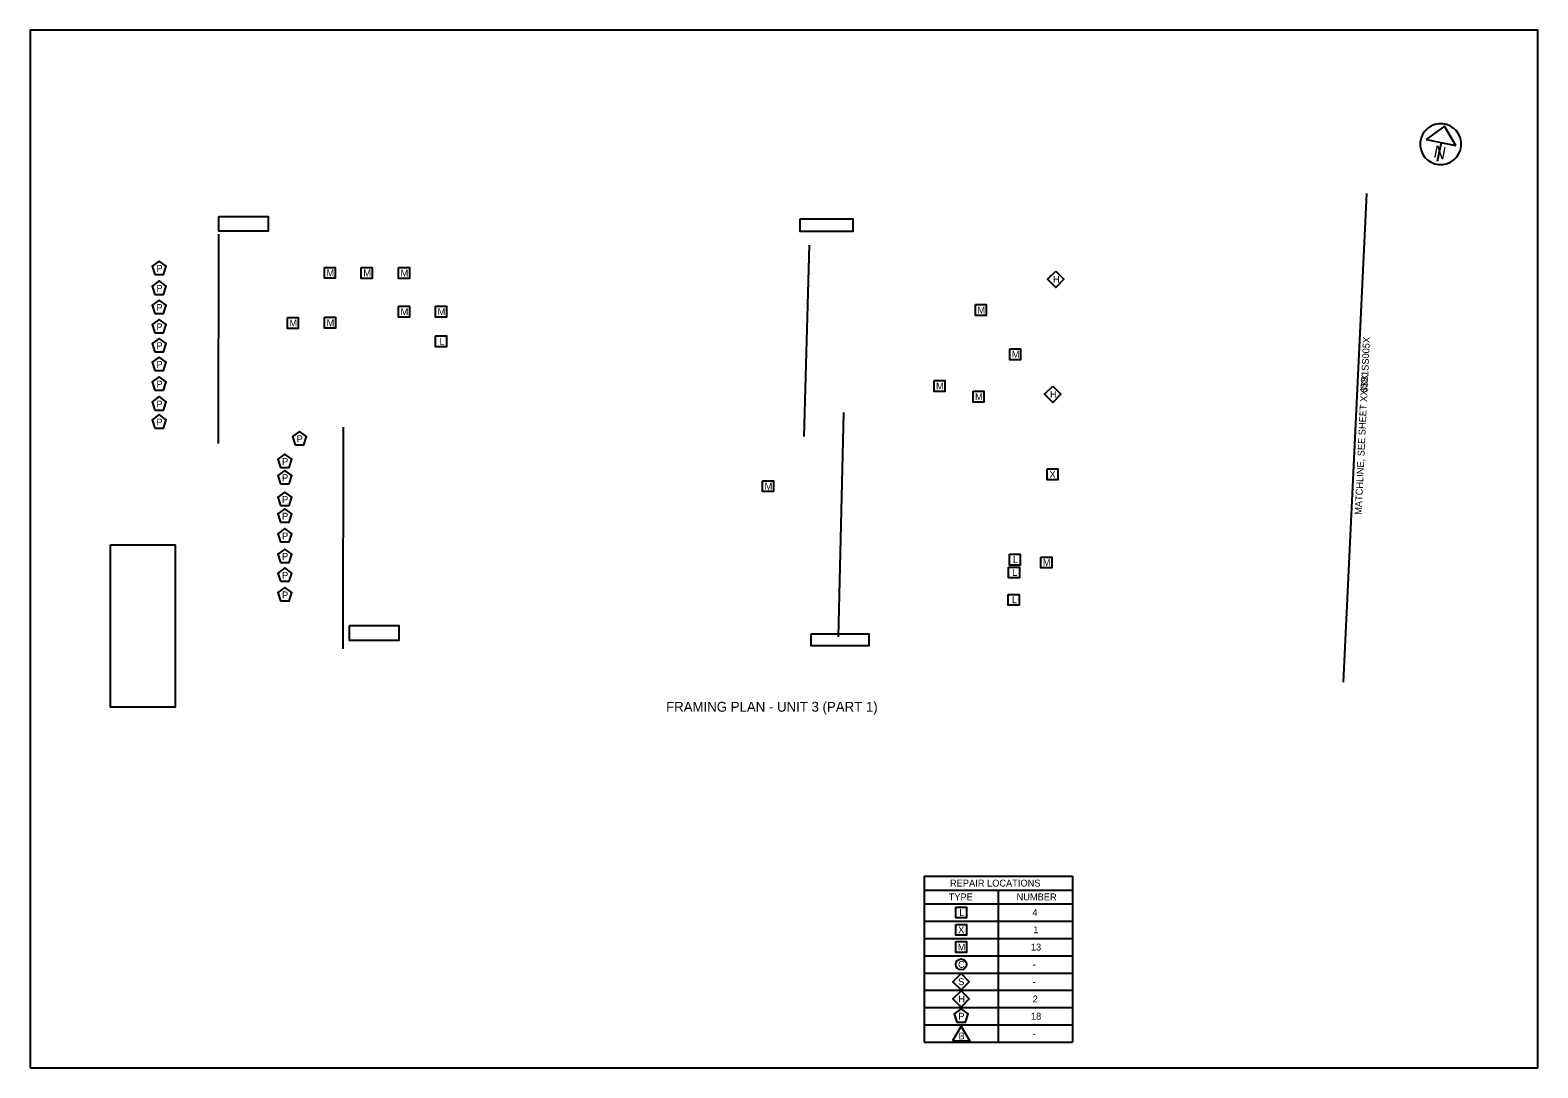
# Model space of a CAD drawing. Extents: x 100 to 130.5, y 100 to 121.
import ezdxf

# ---------------------------------------------------------------- set-up
doc = ezdxf.new("R2010")
doc.units = 0
for name, color, linetype in [('BR_P_Gen_Text', 7, 'Continuous'), ('BR_X_Sub_Centerline', 7, 'Continuous'), ('BR_X_Sub_Text', 7, 'Continuous'), ('SC_Scratch1', 7, 'Continuous'), ('SH_Data', 7, 'Continuous'), ('SH_Masking', 7, 'Continuous')]:
    doc.layers.add(name, color=color, linetype=linetype)

msp = doc.modelspace()

# ---------------------------------------------------------------- linework, layer by layer
at = {"layer": 'BR_P_Gen_Text'}
for p, q in [((127.033, 117.693), (126.562, 107.807)), ((118.083, 103.879), (118.083, 100.519)), ((118.083, 103.879), (121.083, 103.879)), ((121.083, 103.879), (121.083, 100.519)), ((118.083, 103.599), (121.083, 103.599)), ((119.583, 103.599), (119.583, 100.519)), ((118.083, 103.319), (121.083, 103.319)), ((118.083, 102.969), (121.083, 102.969)), ((118.083, 102.619), (121.083, 102.619)), ((118.083, 102.269), (121.083, 102.269)), ((118.083, 101.919), (121.083, 101.919)), ((118.083, 101.569), (121.083, 101.569)), ((118.083, 101.219), (121.083, 101.219)), ((118.083, 100.869), (121.083, 100.869)), ((118.083, 100.519), (121.083, 100.519))]:
    msp.add_line(p, q, dxfattribs=at)
for points in [[(102.523, 116.055), (102.699, 116.055), (102.753, 116.223), (102.611, 116.327), (102.468, 116.223)], [(102.523, 115.653), (102.699, 115.653), (102.753, 115.82), (102.611, 115.924), (102.468, 115.82)], [(105.952, 116.199), (106.172, 116.199), (106.172, 115.979), (105.952, 115.979)], [(106.698, 116.197), (106.918, 116.197), (106.918, 115.977), (106.698, 115.977)], [(107.452, 116.194), (107.672, 116.194), (107.672, 115.974), (107.452, 115.974)], [(120.748, 116.123), (120.913, 115.958), (120.748, 115.793), (120.583, 115.958)], [(102.523, 115.265), (102.699, 115.265), (102.753, 115.433), (102.611, 115.536), (102.468, 115.433)], [(107.452, 115.413), (107.672, 115.413), (107.672, 115.193), (107.452, 115.193)], [(108.202, 115.413), (108.422, 115.413), (108.422, 115.193), (108.202, 115.193)], [(119.122, 115.445), (119.342, 115.445), (119.342, 115.225), (119.122, 115.225)], [(102.523, 114.874), (102.699, 114.874), (102.753, 115.042), (102.611, 115.145), (102.468, 115.042)], [(105.203, 115.184), (105.423, 115.184), (105.423, 114.964), (105.203, 114.964)], [(105.954, 115.189), (106.174, 115.189), (106.174, 114.969), (105.954, 114.969)], [(102.523, 114.492), (102.699, 114.492), (102.753, 114.66), (102.611, 114.763), (102.468, 114.66)], [(108.202, 114.813), (108.422, 114.813), (108.422, 114.593), (108.202, 114.593)], [(102.523, 114.113), (102.699, 114.113), (102.753, 114.28), (102.611, 114.384), (102.468, 114.28)], [(119.817, 114.551), (120.037, 114.551), (120.037, 114.331), (119.817, 114.331)], [(102.523, 113.716), (102.699, 113.716), (102.753, 113.884), (102.611, 113.987), (102.468, 113.884)], [(118.285, 113.909), (118.505, 113.909), (118.505, 113.689), (118.285, 113.689)], [(120.686, 113.795), (120.851, 113.63), (120.686, 113.465), (120.521, 113.63)], [(102.523, 113.312), (102.699, 113.312), (102.753, 113.48), (102.611, 113.584), (102.468, 113.48)], [(119.074, 113.692), (119.294, 113.692), (119.294, 113.472), (119.074, 113.472)], [(102.523, 112.948), (102.699, 112.948), (102.753, 113.116), (102.611, 113.22), (102.468, 113.116)], [(105.36, 112.607), (105.537, 112.607), (105.591, 112.775), (105.449, 112.879), (105.306, 112.775)], [(105.064, 112.148), (105.24, 112.148), (105.294, 112.316), (105.152, 112.42), (105.009, 112.316)], [(105.064, 111.819), (105.24, 111.819), (105.294, 111.987), (105.152, 112.091), (105.009, 111.987)], [(120.571, 112.121), (120.791, 112.121), (120.791, 111.901), (120.571, 111.901)], [(105.064, 111.38), (105.24, 111.38), (105.294, 111.548), (105.152, 111.651), (105.009, 111.548)], [(114.816, 111.881), (115.036, 111.881), (115.036, 111.661), (114.816, 111.661)], [(105.064, 111.042), (105.24, 111.042), (105.294, 111.209), (105.152, 111.313), (105.009, 111.209)], [(105.064, 110.642), (105.24, 110.642), (105.294, 110.81), (105.152, 110.913), (105.009, 110.81)], [(105.064, 110.228), (105.24, 110.228), (105.294, 110.396), (105.152, 110.499), (105.009, 110.396)], [(105.064, 109.846), (105.24, 109.846), (105.294, 110.013), (105.152, 110.117), (105.009, 110.013)], [(119.792, 110.135), (120.012, 110.135), (120.012, 109.915), (119.792, 109.915)], [(119.809, 110.396), (120.029, 110.396), (120.029, 110.176), (119.809, 110.176)], [(120.445, 110.337), (120.665, 110.337), (120.665, 110.117), (120.445, 110.117)], [(105.064, 109.449), (105.24, 109.449), (105.294, 109.617), (105.152, 109.72), (105.009, 109.617)], [(119.788, 109.582), (120.008, 109.582), (120.008, 109.362), (119.788, 109.362)], [(118.723, 103.254), (118.943, 103.254), (118.943, 103.034), (118.723, 103.034)], [(118.723, 102.904), (118.943, 102.904), (118.943, 102.684), (118.723, 102.684)], [(118.723, 102.554), (118.943, 102.554), (118.943, 102.334), (118.723, 102.334)], [(118.833, 101.909), (118.998, 101.744), (118.833, 101.579), (118.668, 101.744)], [(118.833, 101.559), (118.998, 101.394), (118.833, 101.229), (118.668, 101.394)], [(118.745, 100.923), (118.922, 100.923), (118.976, 101.091), (118.833, 101.194), (118.691, 101.091)], [(118.66, 100.544), (119.007, 100.544), (118.833, 100.844)]]:
    msp.add_lwpolyline(points, close=True, dxfattribs=at)
msp.add_circle((118.833, 102.094), 0.11, dxfattribs=at)
at = {"layer": 'BR_X_Sub_Centerline'}
for p, q in [((103.809, 116.871), (103.806, 112.632)), ((115.758, 116.646), (115.651, 112.776)), ((116.355, 108.725), (116.458, 113.261)), ((106.333, 108.477), (106.34, 112.966))]:
    msp.add_line(p, q, dxfattribs=at)
at = {"layer": 'BR_X_Sub_Text'}
for points in [[(103.82, 117.228), (104.818, 117.228), (104.818, 116.931), (103.82, 116.931)], [(115.575, 117.181), (116.64, 117.181), (116.64, 116.926), (115.575, 116.926)], [(106.463, 108.949), (107.456, 108.949), (107.456, 108.648), (106.463, 108.648)], [(115.801, 108.784), (116.967, 108.784), (116.967, 108.543), (115.801, 108.543)]]:
    msp.add_lwpolyline(points, close=True, dxfattribs=at)
at = {"layer": 'SC_Scratch1'}
msp.add_lwpolyline([(100, 100), (130.5, 100), (130.5, 121), (100, 121)], close=True, dxfattribs=at)
at = {"layer": 'SH_Data'}
for p, q in [((128.609, 119.059), (128.24, 118.785)), ((128.843, 118.664), (128.609, 119.059)), ((128.24, 118.785), (128.843, 118.664)), ((128.542, 118.725), (128.466, 118.345))]:
    msp.add_line(p, q, dxfattribs=at)
msp.add_arc((128.535, 118.693), 0.415, 118.4068, 118.3903, dxfattribs=at)
at = {"layer": 'SH_Masking'}
msp.add_lwpolyline([(101.622, 110.583), (102.935, 110.583), (102.935, 107.3), (101.622, 107.3)], close=True, dxfattribs=at)

# ---------------------------------------------------------------- texts
at = {"layer": 'BR_P_Gen_Text'}
for s, height, p in [('P', 0.14, (102.555, 116.107)), ('M', 0.14, (105.994, 116.019)), ('M', 0.14, (106.74, 116.017)), ('M', 0.14, (107.493, 116.014)), ('H', 0.14, (120.691, 115.888)), ('P', 0.14, (102.555, 115.704)), ('P', 0.14, (102.555, 115.316)), ('M', 0.14, (107.493, 115.233)), ('M', 0.14, (108.243, 115.233)), ('M', 0.14, (119.164, 115.265)), ('P', 0.14, (102.555, 114.925)), ('M', 0.14, (105.245, 115.004)), ('M', 0.14, (105.996, 115.009)), ('P', 0.14, (102.555, 114.543)), ('L', 0.14, (108.274, 114.633)), ('M', 0.14, (119.859, 114.371)), ('P', 0.14, (102.555, 114.164)), ('P', 0.14, (102.555, 113.767)), ('M', 0.14, (118.326, 113.729)), ('P', 0.14, (102.555, 113.364)), ('M', 0.14, (119.115, 113.512)), ('H', 0.14, (120.629, 113.56)), ('P', 0.14, (102.555, 113)), ('P', 0.14, (105.392, 112.659)), ('P', 0.14, (105.096, 112.2)), ('P', 0.14, (105.096, 111.871)), ('X', 0.14, (120.62, 111.941)), ('M', 0.14, (114.858, 111.701)), ('P', 0.14, (105.096, 111.431)), ('P', 0.14, (105.096, 111.093)), ('P', 0.14, (105.096, 110.693)), ('P', 0.14, (105.096, 110.279)), ('L', 0.14, (119.881, 110.216)), ('M', 0.14, (120.487, 110.157)), ('P', 0.14, (105.096, 109.897)), ('L', 0.14, (119.864, 109.955)), ('P', 0.14, (105.096, 109.5)), ('L', 0.14, (119.86, 109.402)), ('FRAMING PLAN - UNIT 3 (PART 1)', 0.2, (112.865, 107.207)), ('REPAIR LOCATIONS', 0.14, (118.608, 103.669)), ('TYPE', 0.14, (118.582, 103.389)), ('NUMBER', 0.14, (119.955, 103.389)), ('L', 0.14, (118.795, 103.074)), ('4', 0.14, (120.275, 103.074)), ('X', 0.14, (118.773, 102.724)), ('1', 0.14, (120.294, 102.724)), ('M', 0.14, (118.765, 102.374)), ('13', 0.14, (120.244, 102.374)), ('C', 0.14, (118.771, 102.024)), ('-', 0.14, (120.28, 102.024)), ('S', 0.14, (118.775, 101.674)), ('-', 0.14, (120.28, 101.674)), ('H', 0.14, (118.777, 101.324)), ('2', 0.14, (120.281, 101.324)), ('P', 0.14, (118.777, 100.974)), ('18', 0.14, (120.245, 100.974)), ('B', 0.14, (118.779, 100.574)), ('-', 0.14, (120.28, 100.624))]:
    msp.add_text(s, height=height, dxfattribs=at).set_placement(p)
for s, p in [('$$B1SS005X', (127.052, 113.666)), ('MATCHLINE, SEE SHEET XX/XX', (126.934, 111.189))]:
    msp.add_text(s, height=0.14, rotation=87.2737, dxfattribs=at).set_placement(p)
at = {"layer": 'SH_Data'}
msp.add_text('N', height=0.25, rotation=348.6269, dxfattribs=at).set_placement((128.376, 118.428))

doc.saveas('drawing.dxf')
